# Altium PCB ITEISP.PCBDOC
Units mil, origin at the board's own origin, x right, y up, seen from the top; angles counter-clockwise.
Board outline 1330 x 2302 mil, 2 copper layers (Top Layer, Bottom Layer); 35 components, 63 nets, 132 pads, 0 vias.
Unrouted connection lines stored in the file: 32.
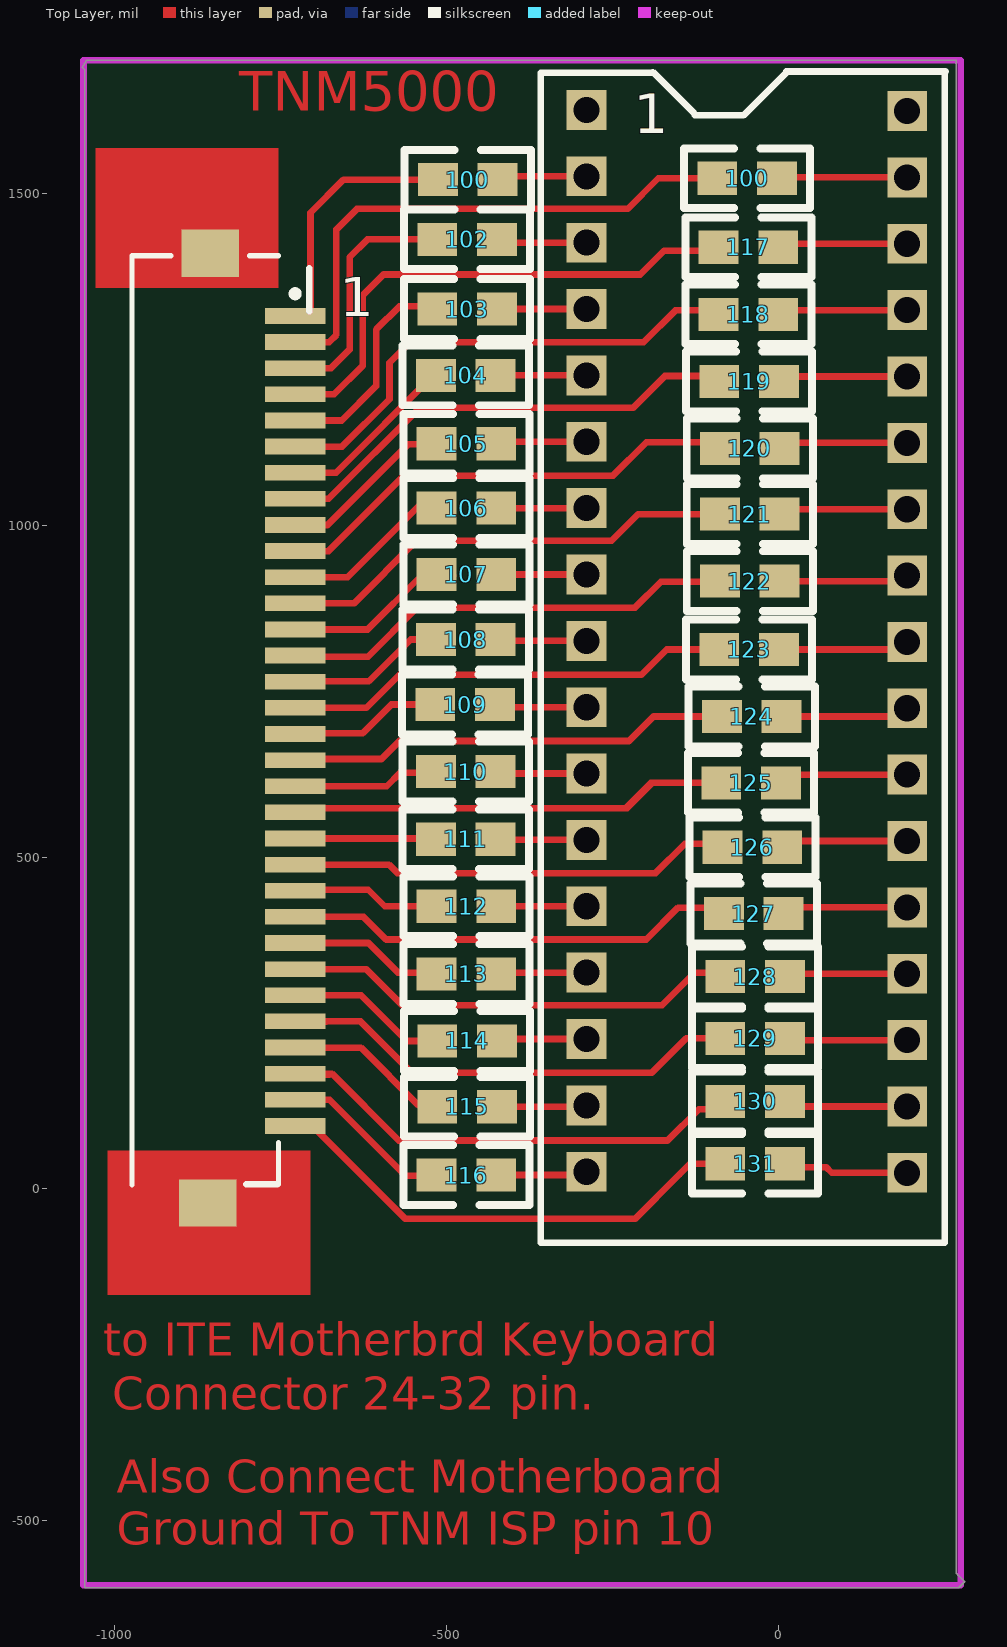
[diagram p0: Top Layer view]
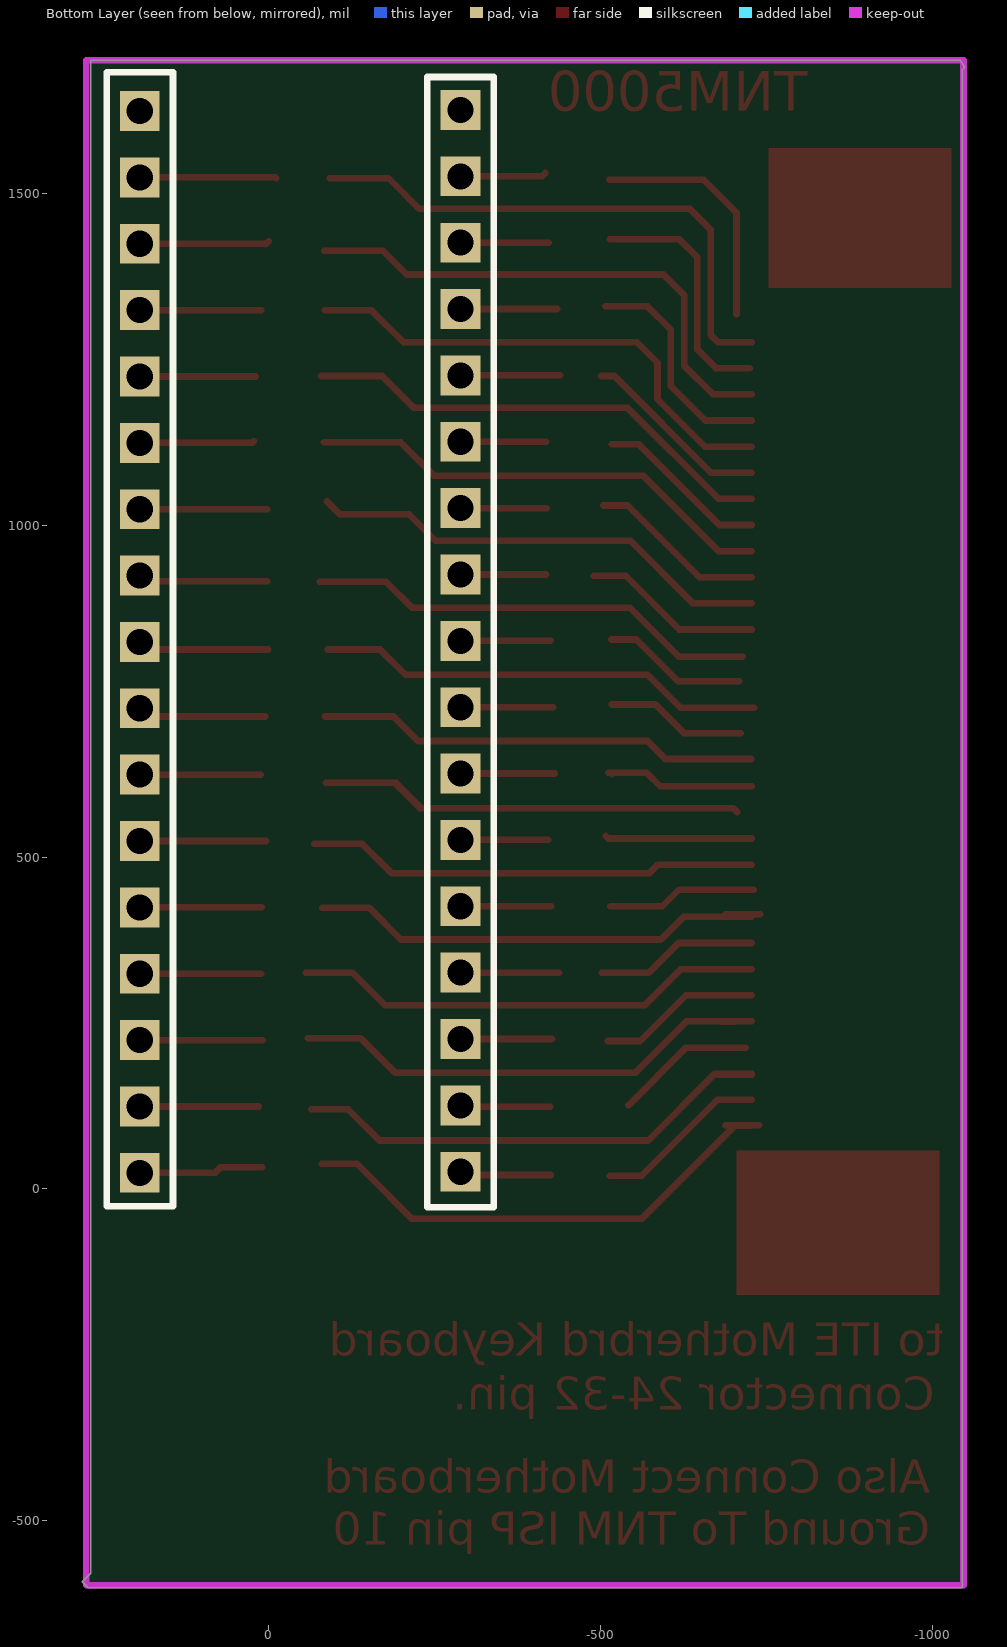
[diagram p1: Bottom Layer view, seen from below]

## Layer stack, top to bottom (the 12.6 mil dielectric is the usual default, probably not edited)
Top Layer: signal copper 1.4
Dielectric: dielectric 12.6, FR-4, Dk 4.8
Bottom Layer: signal copper 1.4

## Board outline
-1042,1701 268,1701 268,-579 281,-592 272,-601 -1045,-601 -1045,1686 -1049,1690

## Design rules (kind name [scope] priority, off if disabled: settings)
Clearance [All] p1: gap=10
ComponentClearance [All] p1 off: gap=10 collisioncheckmode=3 verticalgap=10 showdistances=FALSE
Height [All] p1 off: minheight=0 maxheight=1000 prefheight=500
PolygonConnect [All] p1: connectstyle=Relief reliefconductorwidth=10 reliefentries=4 polygonreliefangle="90 Angle"
RoutingVias [All] p1: holewidth=28 width=50 viastyle="Through Hole" minholewidth=28 minwidth=50 maxholewidth=28 maxwidth=50
ShortCircuit [All] p1: allowed=TRUE
SilkscreenOverComponentPads [All] p1: minsilkscreentomaskgap=10
SolderMaskExpansion [All] p1: expansion=4
UnRoutedNet [All] p1 off:
Width [All] p1: maxlimit=10 minlimit=6 preferedwidth=9.4
23 further rules are at their usual default settings.

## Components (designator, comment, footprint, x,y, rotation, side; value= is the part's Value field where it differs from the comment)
100 "Comment" 0805 -2,1523 r180 top
100 "Comment" 0805 -423,1521 r180 top
102 "Comment" 0805 -424,1431 r180 top
103 "Comment" 0805 -424,1326 r180 top
104 "Comment" 0805 -426,1226 r180 top
105 "Comment" 0805 -425,1123 r180 top
106 "Comment" 0805 -425,1026 r180 top
107 "Comment" 0805 -425,926 r180 top
108 "Comment" 0805 -426,828 r180 top
109 "Comment" 0805 -427,730 r180 top
110 "Comment" 0805 -426,629 r180 top
111 "Comment" 0805 -426,527 r180 top
112 "Comment" 0805 -425,426 r180 top
113 "Comment" 0805 -425,324 r180 top
114 "Comment" 0805 -424,223 r180 top
115 "Comment" 0805 -424,124 r180 top
116 "Comment" 0805 -425,21 r180 top
117 "Comment" 0805 0,1419 r180 top
118 "Comment" 0805 0,1318 r180 top
119 "Comment" 0805 1,1217 r180 top
120 "Comment" 0805 2,1116 r180 top
121 "Comment" 0805 2,1017 r180 top
122 "Comment" 0805 2,916 r180 top
123 "Comment" 0805 1,813 r180 top
124 "Comment" 0805 5,712 r180 top
125 "Comment" 0805 4,612 r180 top
126 "Comment" 0805 6,515 r180 top
127 "Comment" 0805 8,415 r180 top
128 "Comment" 0805 10,320 r180 top
129 "Comment" 0805 10,227 r180 top
130 "Comment" 0805 10,132 r180 top
131 "Comment" 0805 10,38 r180 top
? "10" "PCBComponent_1 - duplicate"#1 194.18,1724.36 r270 bottom
? "10" "PCBComponent_1 - duplicate"#2 -289,1726 r270 bottom
? "Comment" FFC/SM1.0-2H24 -792,853 r270 top

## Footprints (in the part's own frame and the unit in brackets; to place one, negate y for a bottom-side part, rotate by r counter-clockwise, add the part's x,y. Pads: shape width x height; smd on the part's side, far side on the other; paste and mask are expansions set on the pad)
0805 [mil]
  rect 60x50 smd: 1(0,0) 2(90,0)
  silkscreen extent -50,-45 140,45
FFC/SM1.0-2H24 [mm] "Connector; FH12 Series; 24 Position; 1.0mm Spaced Bottom Eccentric Contact"
  rect 0.6x2.316 smd: 1(-11.75,1.625) 2(-10.75,1.625) 3(-9.75,1.625) 4(-8.75,1.625) 5(-7.75,1.625) 6(-6.75,1.625) 7(-5.75,1.625) 8(-4.75,1.625) 9(-3.75,1.625) 10(-2.75,1.625) 11(-1.75,1.625) 12(-0.75,1.625) 13(0.25,1.625) 14(1.25,1.625) 15(2.25,1.625) 16(3.25,1.625) 17(4.25,1.625) 18(5.25,1.625) 19(6.25,1.625) 20(7.25,1.625) 21(8.25,1.625) 22(9.25,1.625) 23(10.25,1.625) 24(11.25,1.625)
  rect 1.8x2.2 smd: 25(22.2,-1.727) 26(-14.15,-1.625)
  silkscreen extent -14.05,-4.62 21.51,1.75
"PCBComponent_1 - duplicate"#1 [mil]
  rect 60x60 hole 39.37: 32(1700,0) 33(1600,0) 34(1500,0) 35(1400,0) 36(1300,0) 37(1200,0) 38(1100,0) 39(1000,0) 40(900,0) 41(800,0) 42(700,0) 43(600,0) 44(500,0) 45(400,0) 46(300,0) 47(200,0) 48(100,0)
  silkscreen extent 41,-50 1750,50
"PCBComponent_1 - duplicate"#2 [mil]
  rect 60x60 hole 39.37: 1(100,0) 2(200,0) 3(300,0) 4(400,0) 5(500,0) 6(600,0) 7(700,0) 8(800,0) 9(900,0) 10(1000,0) 11(1100,0) 12(1200,0) 13(1300,0) 14(1400,0) 15(1500,0) 16(1600,0) 17(1700,0)
  silkscreen extent 50,-50 1753,50

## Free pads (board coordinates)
  rect 91.18x23.62 smd: 25(-728,370.63) 27(-728,291.89) 28(-728,252.52) 29(-728,213.15) 30(-728,173.78) 31(-728,134.41) 32(-728,95.04)
  rect 91x23.62 smd: 26(-728,331.26)

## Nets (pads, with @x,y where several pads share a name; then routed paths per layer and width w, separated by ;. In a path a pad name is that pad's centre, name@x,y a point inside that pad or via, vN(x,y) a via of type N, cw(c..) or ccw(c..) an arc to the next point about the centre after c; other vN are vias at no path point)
ACIN: 
AVCC: 
CLK1: 
CLKPCI: 
FLASHEN: 
GND: 
KSI0: 
KSI1: 
KSI2: 
KSI3: 
KSI4: 
KSI5: 
KSO0: 
KSO1: 
KSO2: 
KSO3: 
KSO4: 
KSO5: 
KSO6: 
KSO7: 
KSO8: 
KSO9: 
LIDON: 
NOVO: 
P1: 100.1@-423,1521 100.2@-513,1521 ?.1@-728.02,1315.6 ?.2@-289,1526 | length 494.8
  Top Layer w10: ?.1@-705,1318 -705,1471 -655,1521 ; -654,1521 100.2@-513,1521 ; 100.1@-417,1531 -412,1526 ?.2@-289,1526
P2: 100.1@-2,1523 100.2@-92,1523 ?.2@-728.02,1276.23 ?.47 | length 1037.1
  Top Layer w10: ?.2@-728.02,1276.23 -676.77,1276.23 -666,1287 -666,1446 -635,1477 -227,1477 -181,1523 100.2@-92,1523 ; 100.1@-11,1523 -9.64,1524.36 ?.47
P3: 102.1 102.2 ?.3 | length 504.8
  Top Layer w10: ?.3@-725,1237 -674,1237 -646,1265 -646,1404 -619,1431 ; -618,1431 102.2 ; 102.1@-422,1426 ?.3@-289,1426
P4: 117.1 117.2 ?.4@-728.02,1197.49 ?.46 | length 991.5
  Top Layer w10: ?.4@-728.02,1197.49 -669.51,1197.49 -626,1241 -626,1347 -595,1378 -208,1378 -172,1414 117.2@-84,1414 ; 117.1@0,1428 3.64,1424.36 ?.46
P5: 103.1 103.2 ?.4@-289,1326 ?.5@-728.02,1158.12 | length 488
  Top Layer w10: ?.5@-728.02,1158.12 -657.88,1158.12 -606,1210 -606,1295 -571,1330 103.2@-507,1330 ; 103.1@-435,1326 ?.4@-289,1326
P6: 118.1 118.2 ?.6@-728.02,1118.75 ?.45 | length 943.6
  Top Layer w10: ?.6@-728.02,1118.75 -657.25,1118.75 -586,1190 -586,1245 -555,1276 -203,1276 -155,1324 118.2@-85,1324 ; 118.1@11,1324 11.36,1324.36 ?.45
P7: 104.1 104.2 ?.5@-289,1226 ?.7@-728.02,1079.38 | length 437.3
  Top Layer w10: ?.7@-728.02,1079.38 -666.62,1079.38 -521,1225 104.2@-501,1225 ; 104.1@-439,1226 ?.5@-289,1226
P8: 119.1 119.2 ?.8@-728.02,1040.01 ?.44 | length 900.2
  Top Layer w10: ?.8@-728.02,1040.01 -677.71,1040.01 -540.72,1177 -219,1177 -171,1225 119.2@-79,1225 ; 119.1@19.64,1224.36 ?.44
P9: 105.1 105.2 ?.6@-289,1126 ?.9@-728.02,1000.64 | length 393.1
  Top Layer w10: ?.9@-728.02,1000.64 -679.36,1000.64 -558,1122 105.2@-517,1122 ; 105.1@-418,1126 -289,1126 ?.6@-291,1128
P10: 120.1 120.2 ?.10@-728.02,961.27 ?.43 | length 886.1
  Top Layer w10: ?.10@-728.02,961.27 -677.73,961.27 -564,1075 -249,1075 -199,1125 120.2@-83,1125 ; 120.1@22,1127 24.64,1124.36 ?.43
P11: 106.1 106.2 ?.7@-289,1026 ?.11@-728.02,921.9 | length 398.8
  Top Layer w10: ?.11@-728.02,921.9 -649.1,921.9 -541,1030 106.2@-504,1030 ; 106.1@-419,1026 ?.7@-289,1026
P12: 121.1 121.2 ?.12@-728.02,882.53 ?.42 | length 895.8
  Top Layer w10: ?.12@-728.02,882.53 -639.47,882.53 -545,977 -251,977 -211,1017 -107,1017 121.2@-88,1036 ; 121.1@2,1024.36 ?.42
P13: 107.1 107.2 ?.8@-289,926 ?.13@-728.02,843.16 | length 400.5
  Top Layer w10: ?.13@-728.02,843.16 -618.84,843.16 -538,924 107.2@-490,924 ; 107.1@-418,926 ?.8@-289,926
P14: 122.1 122.2 ?.14@-728.02,803.79 ?.41 | length 869.8
  Top Layer w10: ?.14@-714,802 -618.21,802 -544.21,876 -216,876 -177,915 122.2@-77,915 ; 122.1 ?.41@188,916
P15: 108.1 108.2 ?.9@-289,826 ?.15@-728.02,764.42 | length 355.1
  Top Layer w10: ?.15@-709,765 -617,765 -554,828 108.2 ; 108.1@-425,826 ?.9@-289,826
P16: 123.1 123.2 ?.16@-728.02,725.05 ?.40 | length 859
  Top Layer w10: ?.16@-732,725 -621,725 -571,775 -207,775 ; -205,776 -168,813 123.2 ; 123.1 ?.40@183,813
P17: 109.1 109.2 ?.10@-289,726 ?.17@-728.02,685.68 | length 351.8
  Top Layer w10: ?.17@-711,687 -626,687 -583,730 109.2 ; 109.1@-429,726 ?.10@-289,726
P18: 124.1 124.2 ?.18 ?.39 | length 852.5
  Top Layer w10: ?.18@-727,648 -598,648 -571,675 -225,675 -188,712 124.2 ; 124.1 ?.39@189,712
P19: 110.1 110.2 ?.11@-289,626 ?.19 | length 367.7
  Top Layer w10: ?.19 -590.06,606.94 -570,627 110.2@-512,627 ; 110.2@-518,625 110.2@-517,626 ; 110.1@-431,626 ?.11@-289,626
P20: 125.1 125.2 ?.20 ?.38 | length 875.8
  Top Layer w10: ?.20@-706,568 -700,574 -230,574 ; 125.2 -190,612 ; 125.1@12.36,624.36 ?.38 ; -230,574 -228,574 -190,612 ; -230,574 -192,612 -190,612
P21: 111.1 111.2 ?.12@-289,526 ?.21 | length 353.6
  Top Layer w10: ?.21 -511.8,528.2 111.2@-508,532 ; 111.1@-421,526 ?.12@-289,526
P22: 126.1 126.2 ?.22 ?.37 | length 873.1
  Top Layer w10: ?.22 -586.83,488.83 -574,476 -185,476 -141,520 126.2@-69,520 ; 126.1@3.64,524.36 ?.37
P23: 112.1 112.2 ?.13@-289,426 ?.23 | length 363.4
  Top Layer w10: ?.23@-731,451 -618,451 -593,426 112.2 ; 112.1@-426,426 ?.13@-289,426
P24: 127.1 127.2 ?.24 ?.36 | length 917.6
  Top Layer w10: ?.24@-741,414 ?.24@-688,414 ; ?.24 -625.09,410.09 -591,376 -199,376 -151,424 127.2@-81,424 ; 127.1@10.64,424.36 ?.36
P25: 113.1 113.2 ?.14@-289,326 pad.25 | length 393.5
  Top Layer w10: pad.25 -617.63,370.63 -573,326 113.2@-502,326 ; 113.1@-438,326 ?.14@-289,326
P26: 128.1 128.2 ?.35 pad.26 | length 897.3
  Top Layer w10: pad.26 -621.26,331.26 -567,277 -175,277 -126,326 128.2@-56,326 ; 128.1@11.64,324.36 ?.35
P27: 114.1 114.2 ?.15@-289,226 pad.27 | length 383.5
  Top Layer w10: pad.27 -628.89,291.89 -560,223 114.2 114.2@-511,223 ; 114.1@-427,226 ?.15@-289,226
P28: 129.1 129.2 ?.34 pad.28 | length 930.2
  Top Layer w10: pad.28 -629.52,252.52 -552,175 -191,175 -139,227 129.2@-59,227 ; pad.28@-703,252 -681,252 ; 129.1@8.64,224.36 ?.34
P29: 115.1 115.2 ?.16@-289,126 pad.29 | length 348
  Top Layer w10: pad.29@-719,213 -629,213 115.2@-542,126 ; 115.1 ?.16@-289,124
P30: 130.1 130.2 ?.33 pad.30 | length 955.4
  Top Layer w10: pad.30@-728,172 -677,172 ; pad.30 -672.78,173.78 -572,73 -167,73 -120,120 130.2@-64,120 ; 130.1@15,124.36 ?.33
P31: 116.1 116.2 ?.17@-289,26 pad.31 | length 396.6
  Top Layer w10: pad.31 -686.41,134.41 -676.41,134.41 -562,20 116.2@-514,20 ; 116.1 -294,21 ?.17@-291,24
P32: 131.1 131.2 ?.32 pad.32 | length 982
  Top Layer w10: pad.32@-739,96 pad.32@-688,96 ; pad.32 -702.04,95.04 -562,-45 -216,-45 -151,20 ; -149,22 -151,20 ; 131.2 -133,38 -151,20 ; 131.1@10,33 72,33 80.64,24.36 ?.32
POWE: 
RST1: 
RST3: 
RSTW: 
VCC: 
VCORE: 
VSB: 
pads on no net: ?.1@-289,1626 ?.25 ?.26 ?.48

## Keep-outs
Keep-Out Layer:
  lines w10: -1047,-597 -1047,1701 275,1701 275,-597 -1047,-597

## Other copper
Top Layer:
  region: -1011,58 -1011,-160 -705,-160 -705,58
  region: -1029,1569 -1029,1358 -753,1358 -753,1569
  text "TNM5000" at -812,1625 h60
  text "to ITE Motherbrd Keyboard" at -1017,-251 h50
  text "Connector 24-32 pin." at -1004,-333 h50
  text "Also Connect Motherboard" at -997,-458 h50
  text "Ground To TNM ISP pin 10" at -997,-536 h50

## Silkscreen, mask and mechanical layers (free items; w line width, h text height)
Top Overlay:
  lines w10: -802,7 -755,7 ; -707,1323 -707,1387 ; -189,1682 -358,1682 -358,-81 251,-81 251,1683 ; -189,1683 -126.5,1620.5 ; -126,1618 -53,1618 ; -51,1619 10,1680 ; 12,1684 252,1684
  text "1" at -218,1591 h60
